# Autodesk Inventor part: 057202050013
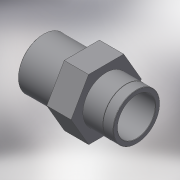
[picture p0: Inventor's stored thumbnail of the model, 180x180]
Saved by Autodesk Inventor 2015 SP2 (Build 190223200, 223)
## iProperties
Created: 2017-10
Part Number: 057202050013
Material: Generic
Description: PLASSON REDUCER THR-CEM REIN 50-(40)-1.1/4"
Document SubType Name: Modeling
Designer: KIM
Density: 1 g/cm^3
Appearance: Default
Author: KIM
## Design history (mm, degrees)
derived "057202.ipt"
feature "Solid1::057202.ipt"
tag "TaggingFeature1"
body "Solid1"
other parameters: "d0" = 68, "d2" = 65, "d3" = 38.952, "d4" = 36, "d6" = 22, "d8" = 46, "d13" = 0, "d14" = 0.4, "d16" = 16, "d17" = 31, "d18" = 26.4, "d19" = 0.1, "d20" = 6.6, "d21" = 46, "G_" = 38.952, "C_" = 65, "B_" = 16, "L_" = 31, "lt_" = 22, "H_" = 68
